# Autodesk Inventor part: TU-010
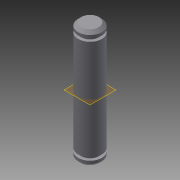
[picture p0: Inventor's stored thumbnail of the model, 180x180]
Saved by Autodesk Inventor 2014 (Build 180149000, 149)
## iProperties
Shininess: 64.0
Angle Display Precision: 2
Document Length Units: 11269
Document Angle Units: 11279
Document Time Units: 11290
Document Mass Units: 11286
Document Length Units Precision: 3
Document Angle Units Precision: 2
Compacted: True
Created: 2002-07
Part Number: TU-010
Document SubType Name: Modeling
Designer: PN
Description: Short Pin
Density: 1 g/cm^3
Mass: 1.9436 g
Surface Area: 11.4919 cm^2
Volume: 1.9436 cm^3
Material: Generic
Appearance: Default
Density: 0.0
Volumn: 0.0
Area: 0.0
PropertySet Name: Model Information
Control State: 0
Master: False
Checked Out: False
LENGTH: 1.000 in
Author: PN
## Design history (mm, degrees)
sketch "Sketch1"
  geometry: L1 (0, 20)-(3, 20); L2 (3, 17)-(4, 17); L3 (3, 18)-(3, 17); L4 (4, 18)-(3, 18); L5 (4, 19)-(4, 18); L6 (3, 20)-(4, 19); L7 (4, 17)-(4, -17); L8 (4, -17)-(3, -17); L9 (3, -17)-(3, -18); L10 (3, -18)-(4, -18); L11 (4, -18)-(4, -19); L12 (4, -19)-(3, -20); L13 (0, 20)-(0, -20); L14 (0, -20)-(3, -20); 1 further point
  constraints: 28 end point, 6 parallel, 5 perpendicular, 1 horizontal, 1 midpoint, 1 vertical
  dimensions: "d4" = 35 distance between parallel lines of L4 L8; "d5" = 1 distance between parallel lines of L4 L2; "d6" = 36 distance between parallel lines of L4 L10; "d7" = 2 distance between parallel lines of L4 L1
revolve "Revolution1" sketch "Sketch1" stored, may be unused: angle "d19" = 90 deg
body "Solid1"
other parameters: "LENGTH" = 25.4 [user parameter]
